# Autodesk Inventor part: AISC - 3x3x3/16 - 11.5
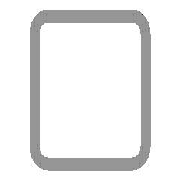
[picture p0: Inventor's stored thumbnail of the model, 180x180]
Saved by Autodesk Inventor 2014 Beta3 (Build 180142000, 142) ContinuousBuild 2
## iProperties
_CCFamilyMember: 9
_CCFamilyDisplayName: ANSI AISC (Square) - Tube
_FrameMemberDoc: Frame Member File
_Version: 15.0.0
_GetPNFromCC: 1
Created: 2010-11
Part Number: AISC - 3x3x3/16 - 11.5
Material: Steel, Mild
Description: Tube
Document SubType Name: Modeling
Standard: ANSI
Designer: Beta-8540w
Standards Organization: ANSI
Language: en-US
Size Designation: 3x3x3/16
Categories: <MemberInstance><Categories><Category DisplayName="Structural Shapes" InternalName="089c4875-fa83-4c05-b084-43b9cc11f5ed" Mnemonic="GRDR"><CategoryParameter Dis
Stock Number: 3x3x3/16
Density: 7.86 g/cm^3
Appearance: Steel
IsCustomPart: 1
G_L: 11.500 in
G_W: 3.000 in
G_H: 3.000 in
Author: Beta-8540w
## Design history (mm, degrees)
node "Start plane"
node "End plane"
sketch "Sketch"
  geometry: L1 (-38.1, -28.575)-(-38.1, 28.575); L2 (-28.575, 38.1)-(28.575, 38.1); L3 (38.1, 28.575)-(38.1, -28.575); L4 (28.575, -38.1)-(-28.575, -38.1); L5 (-28.575, 33.337)-(28.575, 33.338); L6 (33.338, 28.575)-(33.338, -28.575); L7 (28.575, -33.337)-(-28.575, -33.338); L8 (-33.338, -28.575)-(-33.338, 28.575); L9 (0, 56.102)-(0, -56.102) reference; L10 (-56.102, 0)-(56.102, 0) reference; A1 r 9.525 centre (-28.575, -28.575) between (-38.1, -28.575) and (-28.575, -38.1); A2 r 9.525 centre (-28.575, 28.575) between (-28.575, 38.1) and (-38.1, 28.575); A3 r 9.525 centre (28.575, 28.575) between (38.1, 28.575) and (28.575, 38.1); A4 r 9.525 centre (28.575, -28.575) between (28.575, -38.1) and (38.1, -28.575); A5 r 4.763 centre (-28.575, 28.575) between (-28.575, 33.337) and (-33.338, 28.575); A6 r 4.763 centre (28.575, 28.575) between (33.338, 28.575) and (28.575, 33.338); A7 r 4.763 centre (28.575, -28.575) between (28.575, -33.337) and (33.338, -28.575); A8 r 4.763 centre (-28.575, -28.575) between (-33.338, -28.575) and (-28.575, -33.338)
  constraints: 16 end point, 16 point on circle, 8 centre point, 8 tangent, 4 parallel, 3 equal radius, 2 perpendicular, 7 other
  dimensions: "d10" = 76.2 distance between parallel lines of L2 L4 (= G_H); "d11" = 76.2 distance between parallel lines of L1 L3 (= G_W); "d12" = 4.7625 distance between parallel lines of L3 L6 (= G_T); "d15" = 38.1 distance between parallel lines of L2 L10 (= 0.5 x d10); "d16" = 38.1 distance between parallel lines of L9 L3 (= 0.5 x d11); "d17" = 9.525 radius of A1 (= G_IR)
extrude "Body" new body sketch "Sketch" stored distance "d3" = 292.1 (= G_L); taper "d4" = 0 deg
node "Driven Length"
  sketch "Sketch3"
    geometry: L1 (0, 0)-(10, 0) reference
    constraints: 2 end point, 1 horizontal
  workplane "Work Plane3"
  sketch "Sketch4"
    geometry: L1 (-2, 0)-(12, 0) reference; L2 (-2, 292.1)-(12, 292.1) reference
    dimensions: "d19" = 292.1 distance between parallel lines of L1 L2 (derived)
workplane "Work Plane4"
split "Split1"
body "Solid1"
other parameters: "G_W" = 76.2 [user parameter; used in 1 equation term], "G_H" = 76.2 [user parameter; used in 1 equation term], "G_T" = 4.7625 [user parameter; used in 1 equation term], "G_IR" = 9.525 [user parameter; used in 1 equation term], "G_L" = 292.1 (= d19) [user parameter; used in 1 equation term], "G_OFFSET_START" = 0 [user parameter; used in 1 equation term], "G_OFFSET_END" = 38.1 [user parameter; used in 1 equation term], "d13" = 0 (computed from G_OFFSET_START), "d14" = 292.1 (= G_OFFSET_END + B_L), "B_L" = 254 [user parameter; used in 1 equation term], "d18" = 90 deg
